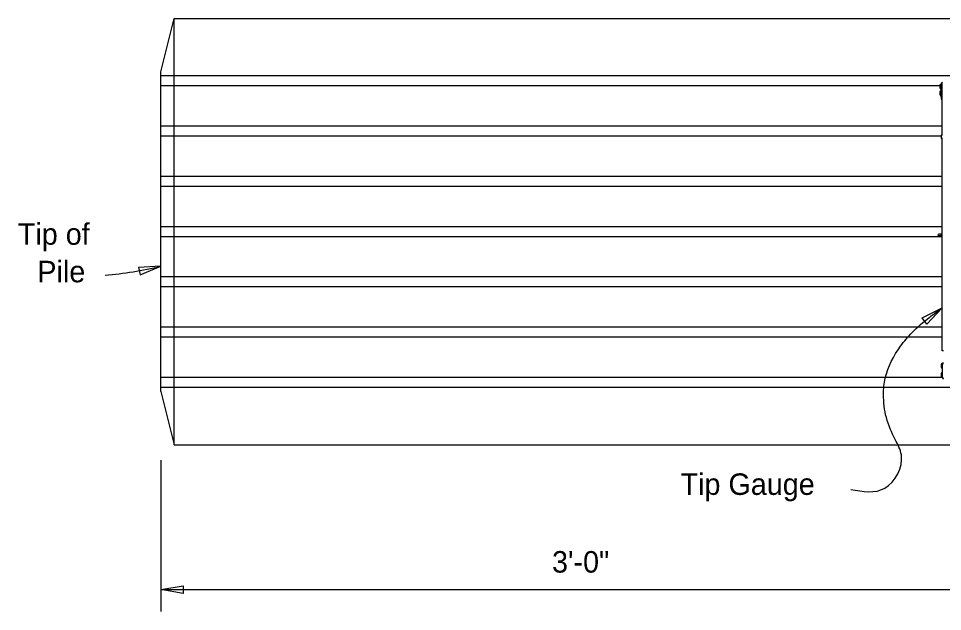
# Model space of a CAD drawing. Extents: x 0 to 36.1, y -3.7 to 15.
# Drawn here: x 0.111 to 4.444, y 9.588 to 12.369 of the extents above; entities that cross this region are included whole.
import ezdxf

# ---------------------------------------------------------------- set-up
doc = ezdxf.new("R2010")
doc.units = 0
for name, color, linetype in [('AdhocPoint_dp', 7, 'Continuous'), ('Leader', 7, 'Continuous'), ('Miscellaneous', 7, 'Continuous'), ('PileConc', 7, 'Continuous'), ('PlotBorder_dp', 7, 'Continuous'), ('PrestressSteel', 7, 'Continuous')]:
    doc.layers.add(name, color=color, linetype=linetype)

msp = doc.modelspace()

# ---------------------------------------------------------------- linework, layer by layer
at = {"layer": 'Leader'}
msp.add_arc((0.366, 12.948), 1.7889, 274.8384, 283.331, dxfattribs=at)
msp.add_spline([(4.0139, 10.1601), (4.1735, 10.1659), (4.2515, 10.3224), (4.2227, 10.3942), (4.1811, 10.4973), (4.1679, 10.6058), (4.1758, 10.6826), (4.2479, 10.8321), (4.3017, 10.8967), (4.3843, 10.9685), (4.4432, 11.0125)], degree=3, dxfattribs=at)
at = {"layer": 'Miscellaneous'}
for p, q in [((4.433, 12.0598), (4.433, 12.0503)), ((4.433, 12.0503), (4.433, 12.0408)), ((4.4342, 12.0607), (4.4382, 12.0607)), ((4.4342, 12.0607), (4.4342, 12.0503)), ((4.4342, 12.0503), (4.4342, 12.0399)), ((4.4432, 12.0621), (4.4382, 12.0621)), ((4.4382, 12.0017), (4.4382, 12.0621)), ((4.4432, 12.0621), (4.4445, 12.0621)), ((4.4432, 12.0017), (4.4432, 12.0621)), ((4.433, 12.0285), (4.433, 12.019)), ((4.433, 12.019), (4.433, 12.0095)), ((4.4382, 12.0399), (4.4342, 12.0399)), ((4.4342, 12.0294), (4.4382, 12.0294)), ((4.4342, 12.0294), (4.4342, 12.019)), ((4.4342, 12.019), (4.4342, 12.0085)), ((4.4382, 12.0085), (4.4342, 12.0085)), ((4.4432, 12.0017), (4.4382, 12.0017)), ((4.4382, 12.0017), (4.4382, 11.9912)), ((4.4382, 11.9912), (4.4432, 11.9912)), ((4.4432, 11.9912), (4.4432, 12.0017)), ((4.4432, 11.822), (4.4432, 11.9916)), ((4.4382, 11.822), (4.4382, 11.8064)), ((4.4447, 11.822), (4.4382, 11.822)), ((4.4447, 11.8064), (4.4382, 11.8064)), ((4.4432, 11.5665), (4.4432, 11.8064)), ((4.4407, 11.5665), (4.4407, 11.3225)), ((4.4445, 11.5665), (4.4407, 11.5665)), ((4.436, 11.3577), (4.4268, 11.3577)), ((4.4403, 11.3577), (4.436, 11.3577)), ((4.4403, 11.3499), (4.4403, 11.3577)), ((4.4403, 11.3577), (4.4407, 11.3577)), ((4.436, 11.3499), (4.4268, 11.3499)), ((4.4403, 11.3499), (4.436, 11.3499)), ((4.4403, 11.3499), (4.4407, 11.3499)), ((4.4445, 11.3225), (4.4407, 11.3225)), ((4.4432, 10.8099), (4.4432, 11.3225)), ((4.4485, 10.8099), (4.4432, 10.8099)), ((4.4392, 10.7494), (4.4392, 10.7304)), ((4.4404, 10.7503), (4.4445, 10.7503)), ((4.4404, 10.7503), (4.4404, 10.7295)), ((4.4445, 10.7537), (4.4485, 10.7537)), ((4.4445, 10.7487), (4.4445, 10.7537)), ((4.4485, 10.7487), (4.4445, 10.7487)), ((4.4445, 10.6843), (4.4445, 10.7487)), ((4.4392, 10.7304), (4.4392, 10.7304)), ((4.4392, 10.7076), (4.4392, 10.6963)), ((4.4404, 10.7295), (4.4404, 10.7294)), ((4.4445, 10.7294), (4.4404, 10.7294)), ((4.4404, 10.7085), (4.4445, 10.7085)), ((4.4404, 10.7085), (4.4404, 10.6961)), ((4.4392, 10.6963), (4.4392, 10.6886)), ((4.4404, 10.6961), (4.4404, 10.6877)), ((4.4445, 10.6877), (4.4404, 10.6877)), ((4.4445, 10.6843), (4.4485, 10.6843))]:
    msp.add_line(p, q, dxfattribs=at)
msp.add_lwpolyline([(4.436, 11.3499), (4.4373, 11.3502), (4.4384, 11.3511), (4.4391, 11.3523), (4.4393, 11.3538), (4.4391, 11.3553), (4.4384, 11.3566), (4.4373, 11.3574), (4.436, 11.3577)], dxfattribs=at)
for centre, radius, start, end in [((4.4685, 12.0503), 0.0367, 164.9997, 195.0003), ((4.4342, 12.0595), 0.00125, 90, 164.9997), ((4.4445, 12.0621), 0.00625, 90, 180), ((4.4445, 12.0621), 0.00125, 90, 180), ((4.4685, 12.019), 0.0367, 164.9997, 195.0003), ((4.4342, 12.0411), 0.00125, 195.0003, 270), ((4.4342, 12.0282), 0.00125, 90, 164.9997), ((4.4342, 12.0098), 0.00125, 195.0003, 270), ((4.4268, 11.3538), 0.00388, 90, 270), ((4.4747, 10.7399), 0.0367, 164.9997, 195.0003), ((4.4404, 10.749), 0.00125, 90, 164.9997), ((4.4747, 10.6981), 0.0367, 164.9997, 195.0003), ((4.4404, 10.7307), 0.00125, 195.0003, 270), ((4.4404, 10.7073), 0.00125, 90, 164.9997), ((4.4404, 10.6889), 0.00125, 195.0003, 270), ((4.4497, 10.6843), 0.00526, 180, 270)]:
    msp.add_arc(centre, radius, start, end, dxfattribs=at)
at = {"layer": 'PileConc'}
for p, q in [((0.7785, 12.1193), (0.841, 12.3693)), ((0.841, 10.3693), (0.841, 12.3693)), ((0.841, 12.3693), (10.1834, 12.3693)), ((0.7785, 10.6193), (0.7785, 12.1193)), ((0.7785, 10.6193), (0.841, 10.3693)), ((0.841, 10.3693), (10.1834, 10.3693))]:
    msp.add_line(p, q, dxfattribs=at)
at = {"layer": 'PlotBorder_dp'}
for p, q in [((0.7785, 10.2978), (0.7785, 9.5876)), ((0.7785, 9.6904), (4.7785, 9.6904))]:
    msp.add_line(p, q, dxfattribs=at)
for points in [[(0.7785, 11.2073), (0.6731, 11.2005), (0.6812, 11.1661)], [(4.4432, 11.0125), (4.3703, 10.9361), (4.3492, 10.9644)], [(0.7785, 9.6904), (0.8826, 9.7081), (0.8826, 9.6728)]]:
    msp.add_lwpolyline(points, close=True, dxfattribs=at)
at = {"layer": 'PrestressSteel'}
for p, q in [((10.1834, 12.1005), (0.7785, 12.1005)), ((4.4319, 12.0536), (0.7785, 12.0536)), ((4.4432, 11.8645), (0.7785, 11.8645)), ((4.4382, 11.8176), (0.7785, 11.8176)), ((4.4432, 11.6286), (0.7785, 11.6286)), ((4.4432, 11.5817), (0.7785, 11.5817)), ((4.4407, 11.3927), (0.7785, 11.3927)), ((4.4407, 11.3458), (0.7785, 11.3458)), ((4.4432, 11.1568), (0.7785, 11.1568)), ((4.4432, 11.1099), (0.7785, 11.1099)), ((4.4432, 10.9208), (0.7785, 10.9208)), ((4.4432, 10.8739), (0.7785, 10.8739)), ((4.4445, 10.685), (0.7785, 10.685)), ((10.1834, 10.6381), (0.7785, 10.6381))]:
    msp.add_line(p, q, dxfattribs=at)

# ---------------------------------------------------------------- texts
at = {"layer": 'AdhocPoint_dp'}
msp.add_text('3\'-0"', height=0.1008, dxfattribs=at).set_placement((2.6131, 9.7702))
at = {"layer": 'PlotBorder_dp'}
for s, p in [('Tip of', (0.1079, 11.3078)), ('Pile', (0.1995, 11.1318)), ('Tip Gauge', (3.2158, 10.1346))]:
    msp.add_text(s, height=0.1008, dxfattribs=at).set_placement(p)

doc.saveas('drawing.dxf')
